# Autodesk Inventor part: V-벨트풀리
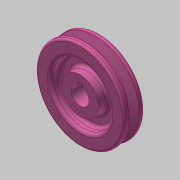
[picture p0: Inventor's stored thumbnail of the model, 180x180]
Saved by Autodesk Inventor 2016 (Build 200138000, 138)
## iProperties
Created: 2018-11
Part Number: V-벨트풀리
Material: 알루미늄 6061
Document SubType Name: Modeling
Designer: mduedu
Density: 1 g/cm^3
Appearance: 분홍색
Author: mduedu
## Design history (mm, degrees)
sketch "스케치1"
  geometry: L1 (-9.5, 0)-(9.5, 0); L2 (9.5, 0)-(9.5, 42.7); L3 (9.5, 42.7)-(-9.5, 42.7); L4 (-9.5, 42.7)-(-9.5, 0); L5 (-4.877, 42.7)-(-1.953, 33.7); L6 (-1.953, 33.7)-(1.953, 33.7); L7 (1.953, 33.7)-(4.877, 42.7); L8 (0, 0)-(0, 42.7); L9 (-9.5, 40)-(9.5, 40); 3 further points
  constraints: 18 end point, 8 point on line, 3 perpendicular, 2 midpoint, 2 parallel, 1 coincident, 1 horizontal, 1 other
  dimensions: "d0" = 85.4 diameter of L3 L1; "d2" = 19 distance of L2.end L3.end; "d3" = 80 diameter of L9 L1; "d4" = 36 deg angle of L7 L5; "d5" = 6.3 distance between parallel lines of L6 L9; "d6" = 8 distance of point (4, 40) point (-4, 40)
revolve "회전1" sketch "스케치1" stored, may be unused: angle "d7" = 90 deg
sketch "스케치2"
  geometry: L1 (-2.5, 8.124)-(2.5, 8.124); L2 (2.5, 8.124)-(2.5, 10.8); L3 (2.5, 10.8)-(-2.5, 10.8); L4 (-2.5, 10.8)-(-2.5, 8.124); A1 r 8.5 centre (0, 0) between (-2.5, 8.124) and (2.5, 8.124); 1 further point
  constraints: 8 end point, 2 parallel, 2 point on circle, 1 centre point, 1 coincident, 1 horizontal, 1 perpendicular
  dimensions: "d8" = 17 diameter of A1; "d10" = 19.3 dimension on A1 L3; "d11" = 5 distance of L2.end L3.end
extrude "돌출1" cut sketch "스케치2" stored distance "d12" = 10; taper "d13" = 0 deg
chamfer "모따기1" distance "d14" = 1; stored, may be unused: second distance "d15" = 2, angle "d16" = 45 deg
fillet "모깎기1" dims "d17" = 1, "d18" = 0.5, "d19" = 2
sketch "스케치3"
  geometry: C1 r 17.5 at (0, 0); C2 r 28.5 at (0, 0); 1 further point
  constraints: 2 centre point, 2 coincident
  dimensions: "d20" = 35 diameter of C1; "d23" = 57 diameter of C2
extrude "돌출2" cut sketch "스케치3" distance "d24" = 9.5; taper "d25" = 0 deg
fillet "모깎기2" dims "d26" = 3
node "솔리드1"
